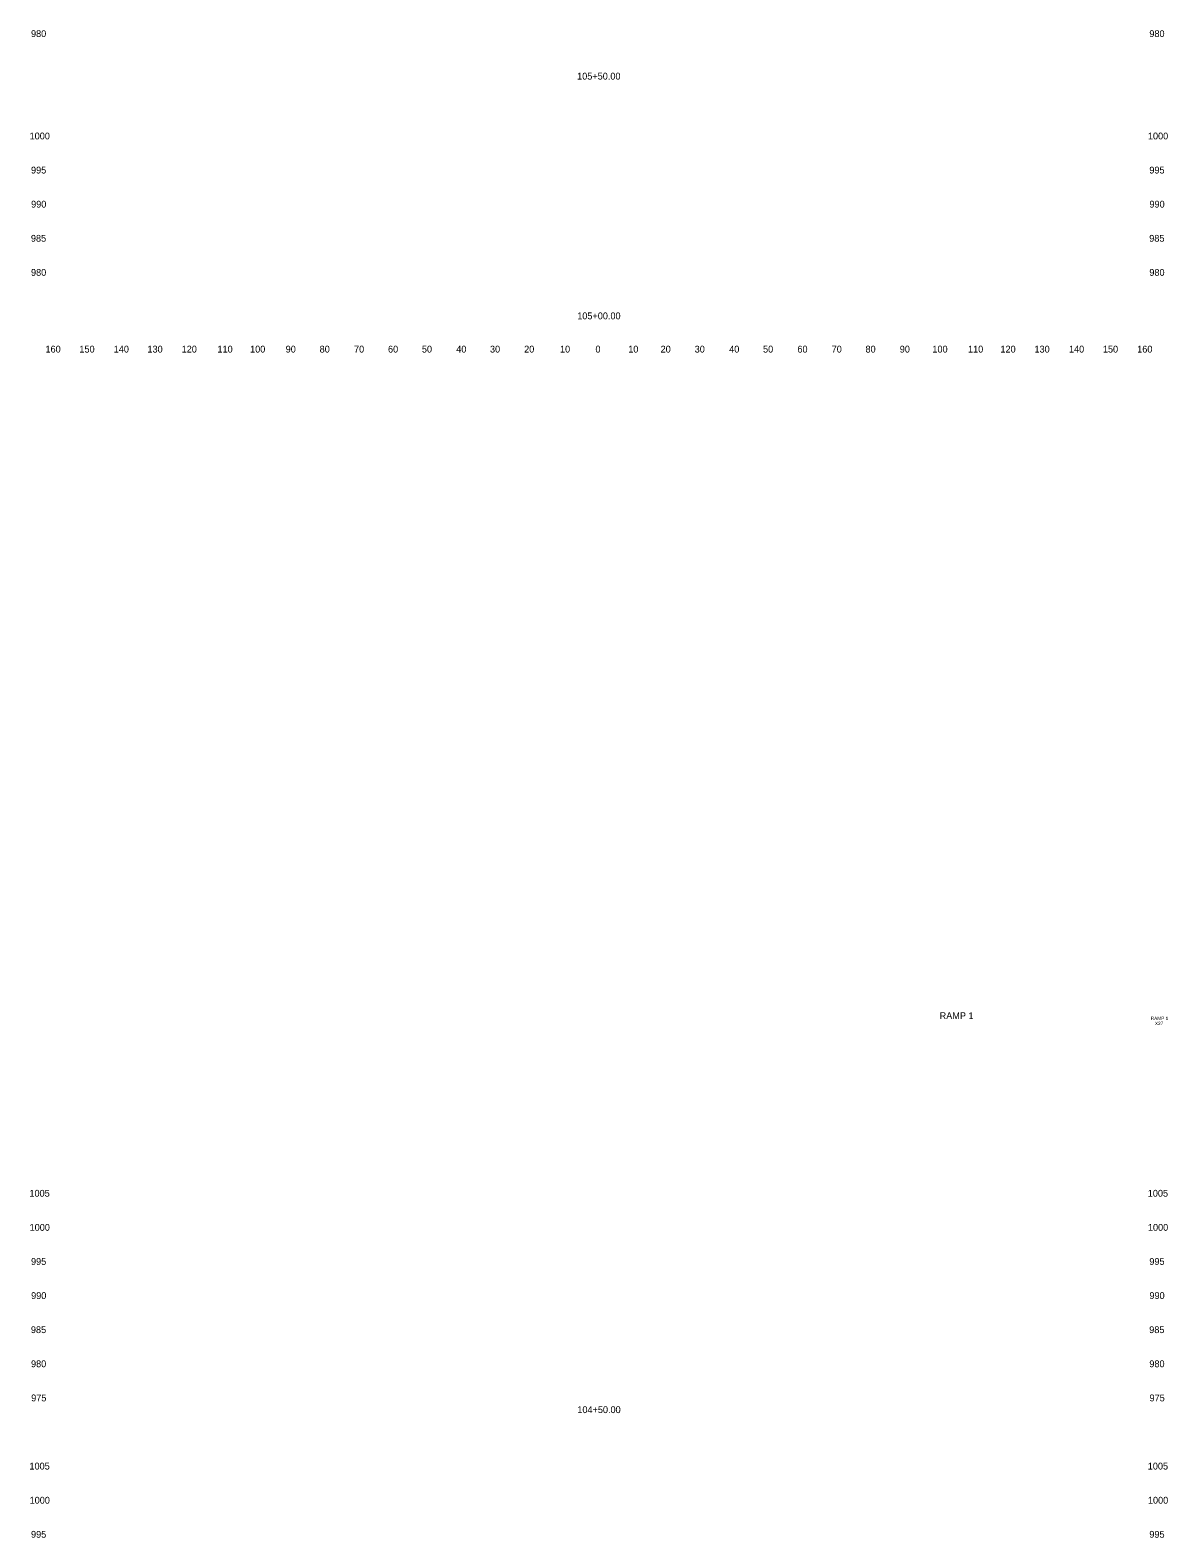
# Model space of a CAD drawing. Extents: x 4994 to 7869, y 4997 to 8804.
# Drawn here: x 6023.6 to 6357.1, y 7450 to 7892 of the extents above; entities that cross this region are included whole.
import ezdxf

# ---------------------------------------------------------------- set-up
doc = ezdxf.new("R2010")
doc.units = 0
for name, color, linetype in [('RD_SHT_ID', 7, 'Continuous'), ('RD_XS_TX_Offset', 7, 'Continuous'), ('RD_XS_TX_Station', 7, 'Continuous')]:
    doc.layers.add(name, color=color, linetype=linetype)

msp = doc.modelspace()

# ---------------------------------------------------------------- texts
at = {"layer": 'RD_SHT_ID'}
for s, height, p in [('RAMP 1', 2, (6290.19, 7602.06)), ('RAMP 1', 1, (6352.06, 7601.8)), ('X27', 1, (6353.29, 7600.3))]:
    msp.add_text(s, height=height, dxfattribs=at).set_placement(p)
at = {"layer": 'RD_XS_TX_Offset'}
for s, p in [('980', (6023.86, 7890)), ('980', (6351.66, 7890)), ('1000', (6023.44, 7860)), ('1000', (6351.24, 7860)), ('995', (6023.86, 7850)), ('995', (6351.66, 7850)), ('990', (6023.89, 7840)), ('990', (6351.69, 7840)), ('985', (6023.83, 7830)), ('985', (6351.63, 7830)), ('980', (6023.86, 7820)), ('980', (6351.66, 7820)), ('160', (6028.1, 7797.5)), ('150', (6038.04, 7797.5)), ('140', (6048.1, 7797.5)), ('130', (6057.99, 7797.5)), ('120', (6068.01, 7797.5)), ('110', (6078.51, 7797.5)), ('100', (6088.07, 7797.5)), ('90', (6098.5, 7797.5)), ('80', (6108.46, 7797.5)), ('70', (6118.54, 7797.5)), ('60', (6128.5, 7797.5)), ('50', (6138.43, 7797.5)), ('40', (6148.5, 7797.5)), ('30', (6158.39, 7797.5)), ('20', (6168.4, 7797.5)), ('10', (6178.91, 7797.5)), ('0', (6189.3, 7797.5)), ('0', (6189.3, 7797.5)), ('10', (6198.91, 7797.5)), ('20', (6208.4, 7797.5)), ('30', (6218.39, 7797.5)), ('40', (6228.5, 7797.5)), ('50', (6238.43, 7797.5)), ('60', (6248.5, 7797.5)), ('70', (6258.54, 7797.5)), ('80', (6268.46, 7797.5)), ('90', (6278.5, 7797.5)), ('100', (6288.07, 7797.5)), ('110', (6298.51, 7797.5)), ('120', (6308.01, 7797.5)), ('130', (6317.99, 7797.5)), ('140', (6328.1, 7797.5)), ('150', (6338.04, 7797.5)), ('160', (6348.1, 7797.5)), ('1005', (6023.4, 7550)), ('1005', (6351.2, 7550)), ('1000', (6023.44, 7540)), ('1000', (6351.24, 7540)), ('995', (6023.86, 7530)), ('995', (6351.66, 7530)), ('990', (6023.89, 7520)), ('990', (6351.69, 7520)), ('985', (6023.83, 7510)), ('985', (6351.63, 7510)), ('980', (6023.86, 7500)), ('980', (6351.66, 7500)), ('975', (6023.91, 7490)), ('975', (6351.71, 7490)), ('1005', (6023.4, 7470)), ('1005', (6351.2, 7470)), ('1000', (6023.44, 7460)), ('1000', (6351.24, 7460)), ('995', (6023.86, 7450)), ('995', (6351.66, 7450))]:
    msp.add_text(s, height=2, dxfattribs=at).set_placement(p)
at = {"layer": 'RD_XS_TX_Station'}
for s, p in [('105+50.00', (6183.93, 7877.54)), ('105+00.00', (6183.96, 7807.26)), ('104+50.00', (6183.99, 7486.55))]:
    msp.add_text(s, height=2, dxfattribs=at).set_placement(p)

doc.saveas('drawing.dxf')
